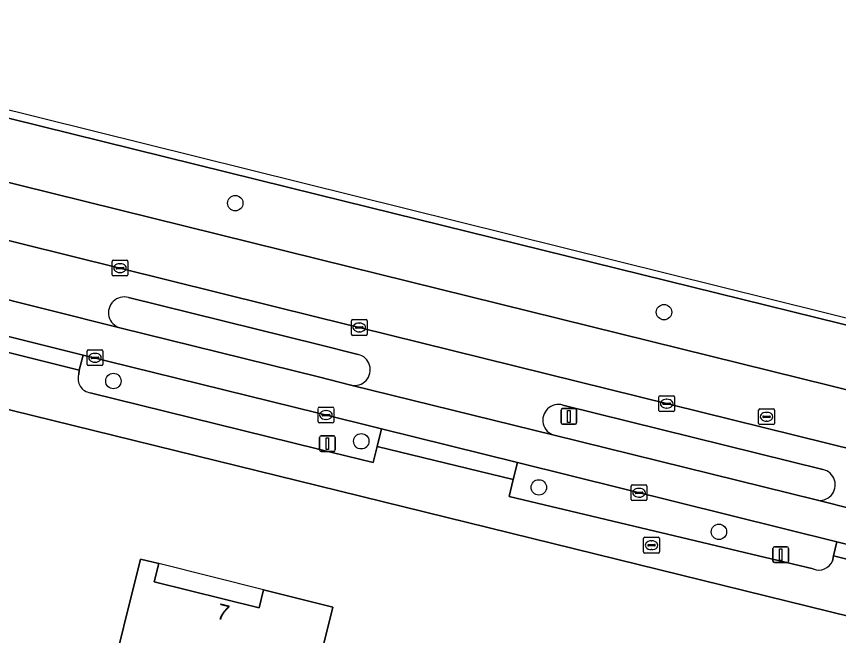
# Model space of a CAD drawing. Extents: x 161139 to 161601, y 381708 to 382245.
# Drawn here: x 161480.8 to 161533, y 382148.6 to 382187.9 of the extents above; entities that cross this region are included whole.
import ezdxf

# ---------------------------------------------------------------- set-up
doc = ezdxf.new("R2010")
doc.units = 0
for name, color, linetype in [('IMGEO_Berm_groen', 7, 'Continuous'), ('IMGEO_Boom', 7, 'Continuous'), ('IMGEO_Brandkraan', 7, 'Continuous'), ('IMGEO_Erf', 7, 'Continuous'), ('IMGEO_Fietspad_gesloten', 7, 'Continuous'), ('IMGEO_Kolk', 7, 'Continuous'), ('IMGEO_Lichtmast', 7, 'Continuous'), ('IMGEO_Pand', 7, 'Continuous'), ('IMGEO_Pand_nummerreeks', 7, 'Continuous'), ('IMGEO_Pand_overbouw', 7, 'Continuous'), ('IMGEO_Parkeervlak_open', 7, 'Continuous'), ('IMGEO_Rijbaan_lokaal_gesloten', 7, 'Continuous'), ('IMGEO_Rioolput', 7, 'Continuous'), ('IMGEO_Voetpad_open', 7, 'Continuous')]:
    doc.layers.add(name, color=color, linetype=linetype)

msp = doc.modelspace()

# ---------------------------------------------------------------- linework, layer by layer
at = {"layer": 'IMGEO_Berm_groen'}
for points in [[(161500, 382176.547), (161460.894, 382186.197), (161420.058, 382196.306), (161417.456, 382196.964), (161416.542, 382193.184), (161418.72, 382192.635), (161459.898, 382182.379), (161500, 382172.465), (161568.862, 382155.44)], [(161575.364, 382159.517), (161571.347, 382159.936), (161562.428, 382161.253), (161560.838, 382161.565), (161558.491, 382162.113), (161500, 382176.547)], [(161502.512, 382166.414), (161500, 382167.036), (161487.941, 382170.021)], [(161487.403, 382168.106), (161500, 382164.986), (161502.062, 382164.475)], [(161485.068, 382166.376), (161484.817, 382165.422), (161484.784, 382165.147)], [(161485.52, 382163.986), (161500, 382160.412), (161503.478, 382159.553), (161503.727, 382160.581), (161504.007, 382161.696), (161500, 382162.686), (161485.068, 382166.376)], [(161532.014, 382159.113), (161515.508, 382163.202)], [(161514.959, 382161.288), (161531.581, 382157.18)], [(161512.622, 382159.561), (161512.36, 382158.471), (161512.101, 382157.407), (161531.397, 382152.805)], [(161532.619, 382153.305), (161532.682, 382153.637), (161532.902, 382154.52), (161512.622, 382159.561)]]:
    msp.add_lwpolyline(points, dxfattribs=at)
for centre, radius, start, end in [((161487.668, 382169.065), 0.995, 74.0907, 254.5249), ((161502.293, 382165.443), 0.995, 256.5514, 77.3169), ((161485.635, 382164.873), 0.894, 162.155, 262.5891), ((161515.229, 382162.246), 0.996, 73.7232, 254.2674), ((161531.802, 382158.145), 0.99, 257.0798, 77.6681), ((161531.749, 382153.687), 0.95, 248.2337, 336.2716)]:
    msp.add_arc(centre, radius, start, end, dxfattribs=at)
at = {"layer": 'IMGEO_Boom'}
for centre in [(161494.721, 382176.011), (161521.926, 382169.098), (161486.986, 382164.728), (161502.714, 382160.905), (161513.981, 382157.98), (161525.411, 382155.161)]:
    msp.add_circle(centre, 0.489, dxfattribs=at)
at = {"layer": 'IMGEO_Brandkraan'}
for p, q in [((161520.632, 382153.886), (161520.632, 382154.738)), ((161520.707, 382154.812), (161521.559, 382154.812)), ((161521.12, 382154.592), (161521.145, 382154.592)), ((161521.633, 382154.738), (161521.633, 382153.886)), ((161520.891, 382154.306), (161520.891, 382154.318)), ((161521.329, 382154.269), (161520.931, 382154.269)), ((161520.934, 382154.355), (161521.332, 382154.355)), ((161521.375, 382154.318), (161521.375, 382154.306)), ((161521.559, 382153.812), (161520.707, 382153.812)), ((161521.143, 382154.032), (161521.118, 382154.032))]:
    msp.add_line(p, q, dxfattribs=at)
for points in [[(161520.632, 382153.886), (161520.632, 382154.738)], [(161520.707, 382154.812), (161521.559, 382154.812)], [(161521.633, 382154.738), (161521.633, 382153.886)], [(161521.559, 382153.812), (161520.707, 382153.812)]]:
    msp.add_lwpolyline(points, dxfattribs=at)
for centre, radius, start, end in [((161520.709, 382154.736), 0.0765, 91.552, 178.448), ((161520.709, 382154.736), 0.0765, 91.552, 178.448), ((161521.557, 382154.736), 0.0765, 1.552, 88.448), ((161521.557, 382154.736), 0.0765, 1.552, 88.448), ((161520.931, 382154.315), 0.0403, 85.8775, 175.7526), ((161520.928, 382154.305), 0.0366, 178.938, 274.7102), ((161521.332, 382154.312), 0.043, 264.8664, 352.4533), ((161521.336, 382154.317), 0.0386, 1.7309, 96.639), ((161520.709, 382153.888), 0.0765, 181.552, 268.448), ((161520.709, 382153.888), 0.0765, 181.552, 268.448), ((161521.557, 382153.888), 0.0765, 271.552, 358.448), ((161521.557, 382153.888), 0.0765, 271.552, 358.448)]:
    msp.add_arc(centre, radius, start, end, dxfattribs=at)
for centre, major_axis, ratio, start_param, end_param in [((161521.119, 382154.312), (-0.387, 0.002), 0.722429, 4.712389, 7.853982), ((161521.144, 382154.312), (-0.39, 0.002), 0.717154, 1.570796, 4.712389)]:
    msp.add_ellipse(centre, major_axis=major_axis, ratio=ratio, start_param=start_param, end_param=end_param, dxfattribs=at)
at = {"layer": 'IMGEO_Erf'}
msp.add_lwpolyline([(161553.295, 382144.911), (161544.61, 382147.101), (161500, 382158.072), (161477.956, 382163.494), (161457.897, 382168.303), (161418.52, 382178.097), (161389.844, 382185.251), (161387.058, 382185.651), (161384.186, 382184.996), (161381.949, 382183.375), (161380.259, 382181.034), (161377.586, 382172.934), (161374.321, 382163.969), (161372.26, 382158.835), (161369.98, 382153.637), (161365.084, 382143.565), (161365.175, 382143.293), (161389.855, 382127.317), (161408.789, 382114.947), (161450.498, 382088.211), (161500, 382056.07), (161523.437, 382040.853), (161561.628, 382099.383), (161581.409, 382129.761)], dxfattribs=at)
msp.add_lwpolyline([(161486.566, 382144.832), (161488.704, 382153.431), (161489.861, 382153.143), (161489.575, 382151.995), (161496.23, 382150.338), (161496.516, 382151.486), (161500.917, 382150.389), (161499.897, 382146.301), (161504.087, 382145.265), (161499.715, 382127.678), (161498.939, 382127.871), (161499.224, 382129.017), (161494.228, 382130.258), (161494.056, 382129.569), (161493.086, 382129.811), (161494.252, 382134.504), (161486.428, 382136.449), (161488.398, 382144.376)], close=True, dxfattribs=at)
at = {"layer": 'IMGEO_Fietspad_gesloten'}
for points in [[(161487.403, 382168.106), (161478.19, 382170.397), (161465.508, 382173.515), (161458.283, 382175.333), (161426.145, 382183.304), (161418.85, 382185.12), (161410.964, 382187.154), (161404.025, 382189.049), (161403.898, 382189.082), (161400.753, 382189.896), (161395.77, 382191.23), (161389.063, 382193.224)], [(161479.47, 382167.765), (161485.068, 382166.376), (161500, 382162.686), (161504.007, 382161.696), (161512.622, 382159.561), (161532.902, 382154.52), (161536.483, 382153.641), (161539.427, 382152.906), (161543.747, 382151.827), (161545.675, 382151.345), (161553.532, 382149.4), (161568.305, 382145.8), (161574.138, 382144.342), (161581.108, 382142.72), (161581.172, 382142.729), (161581.235, 382142.73), (161582.249, 382142.688), (161587.211, 382142.279), (161587.528, 382142.145), (161584.946, 382145.654)], [(161582.536, 382144.993), (161577.725, 382145.856), (161577.59, 382145.885), (161574.358, 382146.578), (161568.691, 382147.976), (161555.792, 382151.158), (161555.682, 382151.185), (161546.127, 382153.566), (161545.639, 382153.688), (161538.79, 382155.377), (161531.581, 382157.18), (161514.959, 382161.288), (161502.062, 382164.475), (161500, 382164.986), (161487.403, 382168.106)]]:
    msp.add_lwpolyline(points, dxfattribs=at)
at = {"layer": 'IMGEO_Kolk'}
for p, q in [((161486.905, 382171.466), (161486.905, 382172.318)), ((161486.98, 382172.392), (161487.832, 382172.392)), ((161487.906, 382172.318), (161487.906, 382171.466)), ((161487.164, 382171.886), (161487.164, 382171.898)), ((161487.602, 382171.849), (161487.204, 382171.849)), ((161487.207, 382171.935), (161487.605, 382171.935)), ((161487.393, 382172.172), (161487.418, 382172.172)), ((161487.648, 382171.898), (161487.648, 382171.886)), ((161487.832, 382171.392), (161486.98, 382171.392)), ((161487.416, 382171.612), (161487.391, 382171.612)), ((161502.09, 382167.698), (161502.09, 382168.55)), ((161502.165, 382168.624), (161503.017, 382168.624)), ((161502.392, 382168.167), (161502.79, 382168.167)), ((161502.578, 382168.404), (161502.603, 382168.404)), ((161503.091, 382168.55), (161503.091, 382167.698)), ((161503.017, 382167.624), (161502.165, 382167.624)), ((161502.349, 382168.118), (161502.349, 382168.13)), ((161502.787, 382168.081), (161502.389, 382168.081)), ((161502.601, 382167.844), (161502.576, 382167.844)), ((161502.833, 382168.13), (161502.833, 382168.118)), ((161485.318, 382165.777), (161485.318, 382166.629)), ((161485.393, 382166.703), (161486.245, 382166.703)), ((161486.319, 382166.629), (161486.319, 382165.777)), ((161485.577, 382166.197), (161485.577, 382166.209)), ((161486.015, 382166.16), (161485.617, 382166.16)), ((161485.62, 382166.246), (161486.018, 382166.246)), ((161485.806, 382166.483), (161485.831, 382166.483)), ((161486.061, 382166.209), (161486.061, 382166.197)), ((161486.245, 382165.703), (161485.393, 382165.703)), ((161485.829, 382165.923), (161485.804, 382165.923)), ((161521.599, 382162.863), (161521.599, 382163.715)), ((161521.674, 382163.789), (161522.526, 382163.789)), ((161522.087, 382163.569), (161522.112, 382163.569)), ((161522.6, 382163.715), (161522.6, 382162.863)), ((161499.972, 382162.143), (161499.972, 382162.995)), ((161500.047, 382163.069), (161500.899, 382163.069)), ((161500.973, 382162.995), (161500.973, 382162.143)), ((161521.858, 382163.283), (161521.858, 382163.295)), ((161522.296, 382163.246), (161521.898, 382163.246)), ((161521.901, 382163.332), (161522.299, 382163.332)), ((161522.11, 382163.009), (161522.085, 382163.009)), ((161522.342, 382163.295), (161522.342, 382163.283)), ((161500.231, 382162.563), (161500.231, 382162.575)), ((161500.669, 382162.526), (161500.271, 382162.526)), ((161500.274, 382162.612), (161500.672, 382162.612)), ((161500.46, 382162.849), (161500.485, 382162.849)), ((161500.715, 382162.575), (161500.715, 382162.563)), ((161522.526, 382162.789), (161521.674, 382162.789)), ((161500.899, 382162.069), (161500.047, 382162.069)), ((161500.483, 382162.289), (161500.458, 382162.289)), ((161519.841, 382157.214), (161519.841, 382158.066)), ((161519.916, 382158.14), (161520.768, 382158.14)), ((161520.329, 382157.92), (161520.354, 382157.92)), ((161520.842, 382158.066), (161520.842, 382157.214)), ((161520.1, 382157.634), (161520.1, 382157.646)), ((161520.538, 382157.597), (161520.14, 382157.597)), ((161520.143, 382157.683), (161520.541, 382157.683)), ((161520.352, 382157.36), (161520.327, 382157.36)), ((161520.584, 382157.646), (161520.584, 382157.634)), ((161520.768, 382157.14), (161519.916, 382157.14))]:
    msp.add_line(p, q, dxfattribs=at)
for points in [[(161486.905, 382171.466), (161486.905, 382172.318)], [(161486.98, 382172.392), (161487.832, 382172.392)], [(161487.906, 382172.318), (161487.906, 382171.466)], [(161487.832, 382171.392), (161486.98, 382171.392)], [(161502.09, 382167.698), (161502.09, 382168.55)], [(161502.165, 382168.624), (161503.017, 382168.624)], [(161503.091, 382168.55), (161503.091, 382167.698)], [(161503.017, 382167.624), (161502.165, 382167.624)], [(161485.318, 382165.777), (161485.318, 382166.629)], [(161485.393, 382166.703), (161486.245, 382166.703)], [(161486.319, 382166.629), (161486.319, 382165.777)], [(161486.245, 382165.703), (161485.393, 382165.703)], [(161521.599, 382162.863), (161521.599, 382163.715)], [(161521.674, 382163.789), (161522.526, 382163.789)], [(161522.6, 382163.715), (161522.6, 382162.863)], [(161499.972, 382162.143), (161499.972, 382162.995)], [(161500.047, 382163.069), (161500.899, 382163.069)], [(161500.973, 382162.995), (161500.973, 382162.143)], [(161522.526, 382162.789), (161521.674, 382162.789)], [(161500.899, 382162.069), (161500.047, 382162.069)], [(161519.841, 382157.214), (161519.841, 382158.066)], [(161519.916, 382158.14), (161520.768, 382158.14)], [(161520.842, 382158.066), (161520.842, 382157.214)], [(161520.768, 382157.14), (161519.916, 382157.14)]]:
    msp.add_lwpolyline(points, dxfattribs=at)
for centre, radius, start, end in [((161486.982, 382172.316), 0.0765, 91.552, 178.448), ((161486.982, 382172.316), 0.0765, 91.552, 178.448), ((161487.83, 382172.316), 0.0765, 1.552, 88.448), ((161487.83, 382172.316), 0.0765, 1.552, 88.448), ((161487.204, 382171.895), 0.0403, 85.8775, 175.7526), ((161487.201, 382171.885), 0.0366, 178.938, 274.7102), ((161487.605, 382171.892), 0.043, 264.8664, 352.4533), ((161487.609, 382171.897), 0.0386, 1.7309, 96.639), ((161486.982, 382171.468), 0.0765, 181.552, 268.448), ((161486.982, 382171.468), 0.0765, 181.552, 268.448), ((161487.83, 382171.468), 0.0765, 271.552, 358.448), ((161487.83, 382171.468), 0.0765, 271.552, 358.448), ((161502.167, 382168.548), 0.0765, 91.552, 178.448), ((161502.167, 382168.548), 0.0765, 91.552, 178.448), ((161502.389, 382168.127), 0.0403, 85.8775, 175.7526), ((161502.794, 382168.129), 0.0386, 1.7309, 96.639), ((161503.015, 382168.548), 0.0765, 1.552, 88.448), ((161503.015, 382168.548), 0.0765, 1.552, 88.448), ((161502.167, 382167.7), 0.0765, 181.552, 268.448), ((161502.167, 382167.7), 0.0765, 181.552, 268.448), ((161502.386, 382168.117), 0.0366, 178.938, 274.7102), ((161502.79, 382168.124), 0.043, 264.8664, 352.4533), ((161503.015, 382167.7), 0.0765, 271.552, 358.448), ((161503.015, 382167.7), 0.0765, 271.552, 358.448), ((161485.395, 382166.627), 0.0765, 91.552, 178.448), ((161485.395, 382166.627), 0.0765, 91.552, 178.448), ((161486.243, 382166.627), 0.0765, 1.552, 88.448), ((161486.243, 382166.627), 0.0765, 1.552, 88.448), ((161485.617, 382166.206), 0.0403, 85.8775, 175.7526), ((161485.614, 382166.196), 0.0366, 178.938, 274.7102), ((161486.018, 382166.203), 0.043, 264.8664, 352.4533), ((161486.022, 382166.208), 0.0386, 1.7309, 96.639), ((161485.395, 382165.779), 0.0765, 181.552, 268.448), ((161485.395, 382165.779), 0.0765, 181.552, 268.448), ((161486.243, 382165.779), 0.0765, 271.552, 358.448), ((161486.243, 382165.779), 0.0765, 271.552, 358.448), ((161521.676, 382163.713), 0.0765, 91.552, 178.448), ((161521.676, 382163.713), 0.0765, 91.552, 178.448), ((161522.524, 382163.713), 0.0765, 1.552, 88.448), ((161522.524, 382163.713), 0.0765, 1.552, 88.448), ((161500.049, 382162.993), 0.0765, 91.552, 178.448), ((161500.049, 382162.993), 0.0765, 91.552, 178.448), ((161500.897, 382162.993), 0.0765, 1.552, 88.448), ((161500.897, 382162.993), 0.0765, 1.552, 88.448), ((161521.898, 382163.292), 0.0403, 85.8775, 175.7526), ((161521.895, 382163.282), 0.0366, 178.938, 274.7102), ((161522.299, 382163.289), 0.043, 264.8664, 352.4533), ((161522.303, 382163.294), 0.0386, 1.7309, 96.639), ((161500.271, 382162.572), 0.0403, 85.8775, 175.7526), ((161500.268, 382162.562), 0.0366, 178.938, 274.7102), ((161500.672, 382162.569), 0.043, 264.8664, 352.4533), ((161500.676, 382162.574), 0.0386, 1.7309, 96.639), ((161521.676, 382162.865), 0.0765, 181.552, 268.448), ((161521.676, 382162.865), 0.0765, 181.552, 268.448), ((161522.524, 382162.865), 0.0765, 271.552, 358.448), ((161522.524, 382162.865), 0.0765, 271.552, 358.448), ((161500.049, 382162.145), 0.0765, 181.552, 268.448), ((161500.049, 382162.145), 0.0765, 181.552, 268.448), ((161500.897, 382162.145), 0.0765, 271.552, 358.448), ((161500.897, 382162.145), 0.0765, 271.552, 358.448), ((161519.918, 382158.064), 0.0765, 91.552, 178.448), ((161519.918, 382158.064), 0.0765, 91.552, 178.448), ((161520.766, 382158.064), 0.0765, 1.552, 88.448), ((161520.766, 382158.064), 0.0765, 1.552, 88.448), ((161519.918, 382157.216), 0.0765, 181.552, 268.448), ((161519.918, 382157.216), 0.0765, 181.552, 268.448), ((161520.14, 382157.643), 0.0403, 85.8775, 175.7526), ((161520.137, 382157.633), 0.0366, 178.938, 274.7102), ((161520.541, 382157.64), 0.043, 264.8664, 352.4533), ((161520.545, 382157.645), 0.0386, 1.7309, 96.639), ((161520.766, 382157.216), 0.0765, 271.552, 358.448), ((161520.766, 382157.216), 0.0765, 271.552, 358.448)]:
    msp.add_arc(centre, radius, start, end, dxfattribs=at)
for centre, major_axis, ratio, start_param, end_param in [((161487.392, 382171.892), (-0.387, 0.002), 0.722429, 4.712389, 7.853982), ((161487.417, 382171.892), (-0.39, 0.002), 0.717154, 1.570796, 4.712389), ((161502.577, 382168.124), (-0.387, 0.002), 0.722429, 4.712389, 7.853982), ((161502.602, 382168.124), (-0.39, 0.002), 0.717154, 1.570796, 4.712389), ((161485.805, 382166.203), (-0.387, 0.002), 0.722429, 4.712389, 7.853982), ((161485.83, 382166.203), (-0.39, 0.002), 0.717154, 1.570796, 4.712389), ((161522.086, 382163.289), (-0.387, 0.002), 0.722429, 4.712389, 7.853982), ((161522.111, 382163.289), (-0.39, 0.002), 0.717154, 1.570796, 4.712389), ((161500.459, 382162.569), (-0.387, 0.002), 0.722429, 4.712389, 7.853982), ((161500.484, 382162.569), (-0.39, 0.002), 0.717154, 1.570796, 4.712389), ((161520.328, 382157.64), (-0.387, 0.002), 0.722429, 4.712389, 7.853982), ((161520.353, 382157.64), (-0.39, 0.002), 0.717154, 1.570796, 4.712389)]:
    msp.add_ellipse(centre, major_axis=major_axis, ratio=ratio, start_param=start_param, end_param=end_param, dxfattribs=at)
at = {"layer": 'IMGEO_Lichtmast'}
for p, q in [((161515.492, 382162.981), (161516.282, 382162.981)), ((161516.282, 382162.981), (161515.492, 382162.981)), ((161515.392, 382162.081), (161515.392, 382162.881)), ((161515.392, 382162.881), (161515.392, 382162.081)), ((161516.382, 382162.881), (161516.382, 382162.081)), ((161516.382, 382162.081), (161516.382, 382162.881)), ((161516.282, 382161.981), (161515.492, 382161.981)), ((161515.492, 382161.981), (161516.282, 382161.981)), ((161500.075, 382160.354), (161500.075, 382161.154)), ((161500.075, 382161.154), (161500.075, 382160.354)), ((161500.175, 382161.254), (161500.965, 382161.254)), ((161500.965, 382161.254), (161500.175, 382161.254)), ((161501.065, 382161.154), (161501.065, 382160.354)), ((161501.065, 382160.354), (161501.065, 382161.154)), ((161500.965, 382160.254), (161500.175, 382160.254)), ((161500.175, 382160.254), (161500.965, 382160.254)), ((161528.837, 382153.308), (161528.837, 382154.108)), ((161528.837, 382154.108), (161528.837, 382153.308)), ((161528.937, 382154.208), (161529.727, 382154.208)), ((161529.727, 382154.208), (161528.937, 382154.208)), ((161529.827, 382154.108), (161529.827, 382153.308)), ((161529.827, 382153.308), (161529.827, 382154.108)), ((161529.727, 382153.208), (161528.937, 382153.208)), ((161528.937, 382153.208), (161529.727, 382153.208))]:
    msp.add_line(p, q, dxfattribs=at)
for points in [[(161515.812, 382162.856), (161515.962, 382162.856), (161515.962, 382162.106), (161515.812, 382162.106), (161515.812, 382162.856)], [(161500.495, 382161.129), (161500.645, 382161.129), (161500.645, 382160.379), (161500.495, 382160.379), (161500.495, 382161.129)], [(161529.257, 382154.083), (161529.407, 382154.083), (161529.407, 382153.333), (161529.257, 382153.333), (161529.257, 382154.083)]]:
    msp.add_lwpolyline(points, dxfattribs=at)
for centre, start, end in [((161515.492, 382162.881), 90, 180), ((161515.492, 382162.881), 90, 180), ((161516.282, 382162.881), 0, 90), ((161516.282, 382162.881), 360, 90), ((161515.492, 382162.081), 180, 270), ((161515.492, 382162.081), 180, 270), ((161516.282, 382162.081), 270, 0), ((161516.282, 382162.081), 270, 0), ((161500.175, 382161.154), 90, 180), ((161500.175, 382161.154), 90, 180), ((161500.965, 382161.154), 0, 90), ((161500.965, 382161.154), 360, 90), ((161500.175, 382160.354), 180, 270), ((161500.175, 382160.354), 180, 270), ((161500.965, 382160.354), 270, 0), ((161500.965, 382160.354), 270, 0), ((161528.937, 382154.108), 90, 180), ((161528.937, 382154.108), 90, 180), ((161529.727, 382154.108), 0, 90), ((161529.727, 382154.108), 360, 90), ((161528.937, 382153.308), 180, 270), ((161528.937, 382153.308), 180, 270), ((161529.727, 382153.308), 270, 0), ((161529.727, 382153.308), 270, 0)]:
    msp.add_arc(centre, 0.1, start, end, dxfattribs=at)
at = {"layer": 'IMGEO_Pand'}
msp.add_lwpolyline([(161504.087, 382145.265), (161499.897, 382146.301), (161500.917, 382150.389), (161496.516, 382151.486), (161496.23, 382150.338), (161489.575, 382151.995), (161489.861, 382153.143), (161488.704, 382153.431), (161486.566, 382144.832), (161488.398, 382144.376), (161486.428, 382136.449), (161494.252, 382134.504), (161493.086, 382129.811), (161494.056, 382129.569), (161494.228, 382130.258), (161499.224, 382129.017), (161498.939, 382127.871), (161499.715, 382127.678)], close=True, dxfattribs=at)
at = {"layer": 'IMGEO_Pand_overbouw'}
msp.add_lwpolyline([(161496.516, 382151.486), (161489.861, 382153.143), (161489.575, 382151.995), (161496.23, 382150.338)], close=True, dxfattribs=at)
at = {"layer": 'IMGEO_Parkeervlak_open'}
for points in [[(161502.587, 382168.125), (161500, 382168.766), (161459.102, 382178.908), (161420.449, 382188.487), (161415.442, 382189.785), (161412.878, 382190.505)], [(161478.19, 382170.397), (161487.403, 382168.106)], [(161487.941, 382170.021), (161500, 382167.036), (161502.512, 382166.414)], [(161571.771, 382151.019), (161502.587, 382168.125)], [(161502.062, 382164.475), (161514.959, 382161.288)], [(161515.508, 382163.202), (161532.014, 382159.113)], [(161531.581, 382157.18), (161538.79, 382155.377), (161545.639, 382153.688), (161546.127, 382153.566)]]:
    msp.add_lwpolyline(points, dxfattribs=at)
for centre, radius, start, end in [((161487.668, 382169.065), 0.995, 74.0907, 254.5249), ((161502.293, 382165.443), 0.995, 256.5514, 77.3169), ((161515.229, 382162.246), 0.996, 73.7232, 254.2674), ((161531.802, 382158.145), 0.99, 257.0798, 77.6681)]:
    msp.add_arc(centre, radius, start, end, dxfattribs=at)
at = {"layer": 'IMGEO_Rijbaan_lokaal_gesloten'}
for points in [[(161371.295, 382209.7), (161379.73, 382204.16), (161385.013, 382201.164), (161389.691, 382198.806), (161397.081, 382195.854), (161402.036, 382194.12), (161402.198, 382194.055), (161405.248, 382192.835), (161406.546, 382192.371), (161409.616, 382191.449), (161412.637, 382190.575), (161412.768, 382190.537), (161412.878, 382190.505), (161415.442, 382189.785), (161420.449, 382188.487), (161459.102, 382178.908), (161500, 382168.766), (161502.587, 382168.125), (161571.771, 382151.019), (161574.719, 382150.267), (161575.117, 382154.078)], [(161575.538, 382161.247), (161562.018, 382161.64), (161415.973, 382197.911)], [(161568.862, 382155.44), (161500, 382172.465), (161459.898, 382182.379), (161418.72, 382192.635), (161416.542, 382193.184)], [(161460.894, 382186.197), (161500, 382176.547), (161558.491, 382162.113), (161560.838, 382161.565), (161562.428, 382161.253), (161571.347, 382159.936), (161575.364, 382159.517), (161575.538, 382161.247)]]:
    msp.add_lwpolyline(points, dxfattribs=at)
at = {"layer": 'IMGEO_Rioolput'}
for p, q in [((161528.006, 382162.96), (161528.858, 382162.96)), ((161527.931, 382162.034), (161527.931, 382162.886)), ((161528.19, 382162.454), (161528.19, 382162.466)), ((161528.628, 382162.417), (161528.23, 382162.417)), ((161528.233, 382162.503), (161528.631, 382162.503)), ((161528.419, 382162.74), (161528.444, 382162.74)), ((161528.674, 382162.466), (161528.674, 382162.454)), ((161528.932, 382162.886), (161528.932, 382162.034)), ((161528.858, 382161.96), (161528.006, 382161.96)), ((161528.442, 382162.18), (161528.417, 382162.18))]:
    msp.add_line(p, q, dxfattribs=at)
for points in [[(161528.006, 382162.96), (161528.858, 382162.96)], [(161527.931, 382162.034), (161527.931, 382162.886)], [(161528.932, 382162.886), (161528.932, 382162.034)], [(161528.858, 382161.96), (161528.006, 382161.96)]]:
    msp.add_lwpolyline(points, dxfattribs=at)
for centre, radius, start, end in [((161528.008, 382162.884), 0.0765, 91.552, 178.448), ((161528.008, 382162.884), 0.0765, 91.552, 178.448), ((161528.856, 382162.884), 0.0765, 1.552, 88.448), ((161528.856, 382162.884), 0.0765, 1.552, 88.448), ((161528.23, 382162.463), 0.0403, 85.8775, 175.7526), ((161528.227, 382162.453), 0.0366, 178.938, 274.7102), ((161528.631, 382162.46), 0.043, 264.8664, 352.4533), ((161528.635, 382162.465), 0.0386, 1.7309, 96.639), ((161528.008, 382162.036), 0.0765, 181.552, 268.448), ((161528.008, 382162.036), 0.0765, 181.552, 268.448), ((161528.856, 382162.036), 0.0765, 271.552, 358.448), ((161528.856, 382162.036), 0.0765, 271.552, 358.448)]:
    msp.add_arc(centre, radius, start, end, dxfattribs=at)
for centre, major_axis, ratio, start_param, end_param in [((161528.418, 382162.46), (-0.387, 0.002), 0.722429, 4.712389, 7.853982), ((161528.443, 382162.46), (-0.39, 0.002), 0.717154, 1.570796, 4.712389)]:
    msp.add_ellipse(centre, major_axis=major_axis, ratio=ratio, start_param=start_param, end_param=end_param, dxfattribs=at)
at = {"layer": 'IMGEO_Voetpad_open'}
for points in [[(161378.971, 382187.245), (161387.058, 382185.651), (161389.844, 382185.251), (161418.52, 382178.097), (161457.897, 382168.303), (161477.956, 382163.494), (161500, 382158.072), (161544.61, 382147.101), (161553.295, 382144.911), (161577.621, 382138.939), (161579.137, 382138.37), (161582.049, 382137.272), (161581.211, 382138.152), (161576.782, 382142.804)], [(161484.784, 382165.147), (161484.817, 382165.422), (161479.208, 382166.815), (161478.917, 382165.631), (161463.743, 382169.384)], [(161531.397, 382152.805), (161512.101, 382157.407), (161512.36, 382158.471), (161503.727, 382160.581), (161503.478, 382159.553), (161500, 382160.412), (161485.52, 382163.986)], [(161543.482, 382150.599), (161543.551, 382151.041), (161539.24, 382152.141), (161538.923, 382150.852), (161535.94, 382151.584), (161536.22, 382152.756), (161532.682, 382153.637), (161532.619, 382153.305)]]:
    msp.add_lwpolyline(points, dxfattribs=at)
for points in [[(161479.47, 382167.765), (161479.208, 382166.815), (161484.817, 382165.422), (161485.068, 382166.376)], [(161512.36, 382158.471), (161512.622, 382159.561), (161504.007, 382161.696), (161503.727, 382160.581)], [(161532.682, 382153.637), (161536.22, 382152.756), (161536.483, 382153.641), (161532.902, 382154.52)]]:
    msp.add_lwpolyline(points, close=True, dxfattribs=at)
for centre, radius, start, end in [((161485.635, 382164.873), 0.894, 162.155, 262.5891), ((161531.749, 382153.687), 0.95, 248.2337, 336.2716)]:
    msp.add_arc(centre, radius, start, end, dxfattribs=at)

# ---------------------------------------------------------------- texts
at = {"layer": 'IMGEO_Pand_nummerreeks'}
msp.add_text('7', height=1, rotation=346.0026, dxfattribs=at).set_placement((161493.476, 382149.667))

doc.saveas('drawing.dxf')
